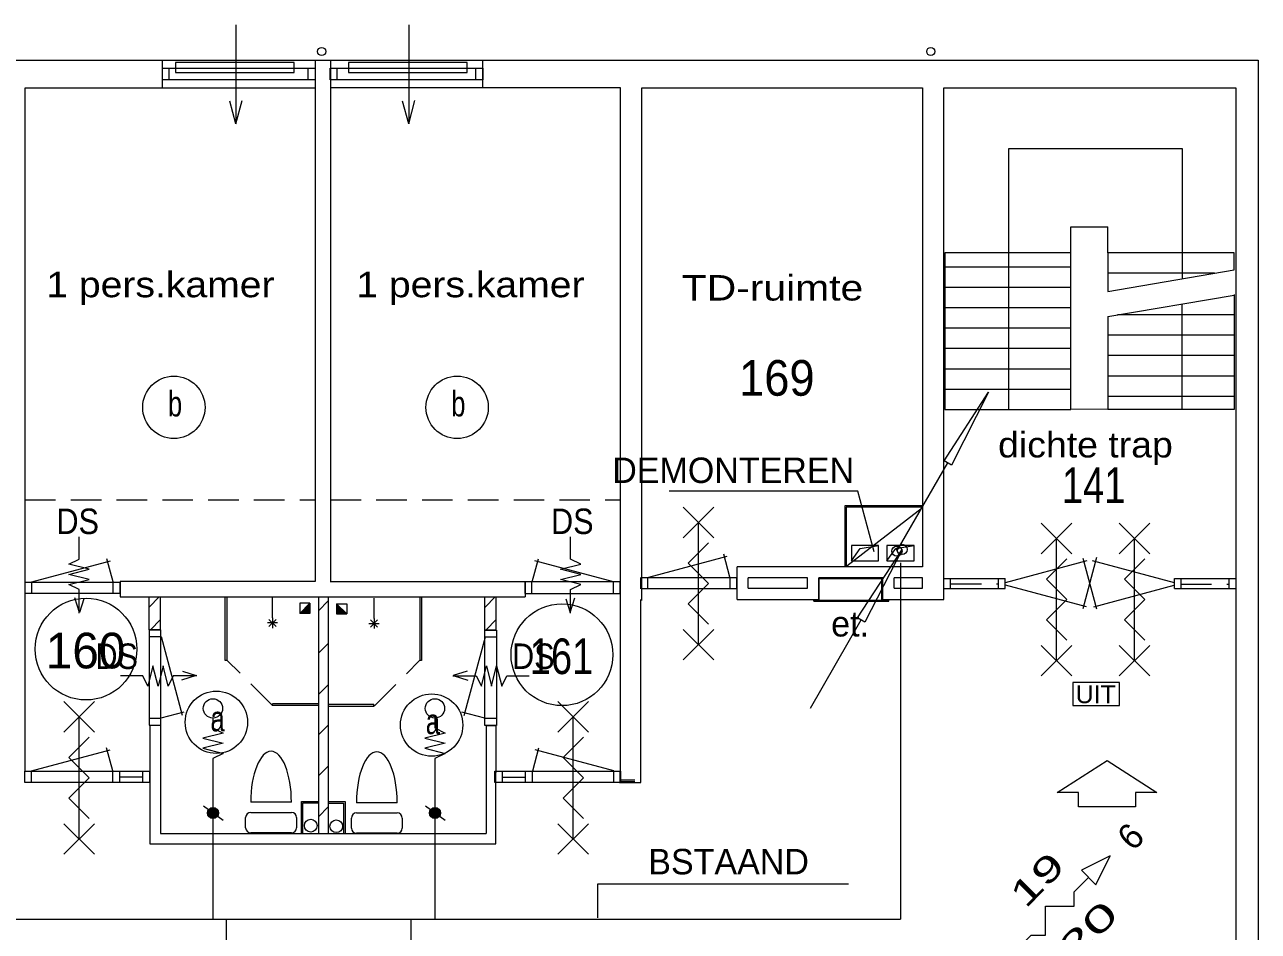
# Model space of a CAD drawing. Extents: x 295824 to 414724, y 24924 to 109024.
# Drawn here: x 320086 to 332210, y 70606 to 79510 of the extents above; entities that cross this region are included whole.
import ezdxf
from ezdxf.enums import TextEntityAlignment as Align

# ---------------------------------------------------------------- set-up
doc = ezdxf.new("R2010")
doc.units = 0
doc.header["$LTSCALE"] = 100
doc.linetypes.add('MEDIUM_DASHED', pattern=[4.5, 3, -1.5])
for name, color, linetype, lineweight in [('1', 7, 'Continuous', 13), ('16', 7, 'Continuous', 13), ('24', 7, 'Continuous', 13), ('61', 7, 'Continuous', 13)]:
    doc.layers.add(name, color=color, linetype=linetype, lineweight=lineweight)

msp = doc.modelspace()

# ---------------------------------------------------------------- hatches: boundary and pattern name
at = {"layer": '24'}
for points in [[(321990.4, 71768.1, 1), (321881.8, 71768.1, 1)], [(324172.4, 71768.1, 1), (324063.7, 71768.1, 1)]]:
    msp.add_hatch(color=256, dxfattribs=at).paths.add_polyline_path(points)
at = {"layer": '61'}
for points in [[(322789.4, 73728.2), (322889.4, 73828.2), (322889.4, 73728.2)], [(323251.9, 73722.8), (323151.9, 73822.8), (323151.9, 73722.8)]]:
    msp.add_hatch(color=256, dxfattribs=at).paths.add_polyline_path(points)

# ---------------------------------------------------------------- linework, layer by layer
at = {"layer": '1'}
for p, q in [((328658.4, 74340.1), (329158.4, 75206.1)), ((327808.4, 72797.7), (328308.4, 73663.7)), ((321936.1, 71736.8), (321936.1, 70726.3)), ((324118, 71730.1), (324118, 70726.3)), ((322069.3, 69843.4), (322069.3, 70726.3)), ((323884.9, 69838.4), (323884.9, 70726.3))]:
    msp.add_line(p, q, dxfattribs=at)
for points in [[(329558.4, 75899.1), (329194.4, 75185.1), (329122.4, 75227.1)], [(328708.4, 74356.7), (328344.4, 73642.7), (328272.4, 73684.7)]]:
    msp.add_lwpolyline(points, close=True, dxfattribs=at)
msp.add_lwpolyline([(328433.5, 74331.1), (328273.3, 74928.7), (326419.8, 74928.7)], dxfattribs=at)
for centre in [(328658.4, 74339.8), (328708.4, 74356.4)]:
    msp.add_circle(centre, 50, dxfattribs=at)
at = {"layer": '16'}
for p, q in [((320520.3, 74111.7), (320720.3, 74161.7)), ((325550.6, 74111.7), (325350.6, 74161.7)), ((321396.7, 73013.5), (321346.7, 73213.5)), ((324674.2, 73013.5), (324724.2, 73213.5))]:
    msp.add_line(p, q, dxfattribs=at)
at = {"layer": '24'}
for p, q in [((322161, 78534.5), (322101.4, 78756.9)), ((323859.9, 78534.5), (323800.3, 78756.9)), ((328693.9, 74223.5), (328693.9, 70726.3)), ((320623.7, 73736.3), (320578.6, 73880.4)), ((320666.1, 73872.1), (320623.7, 73736.3)), ((325404.8, 73872.1), (325447.2, 73736.3)), ((325447.2, 73736.3), (325492.2, 73880.4)), ((321772.1, 73116.9), (321627.9, 73071.9)), ((321636.3, 73159.3), (321772.1, 73116.9)), ((324434.5, 73159.3), (324298.7, 73116.9)), ((324298.7, 73116.9), (324442.9, 73071.9)), ((321936.1, 72253.5), (321936.1, 71714.1)), ((324118, 72253.5), (324118, 71745.1)), ((321844.5, 71838.9), (322036, 71697.3)), ((324026.4, 71838.9), (324218, 71697.3)), ((304097.2, 70726.3), (328693.9, 70726.3))]:
    msp.add_line(p, q, dxfattribs=at)
for points in [[(322161, 79509.5), (322161, 78534.5), (322222.6, 78764.7)], [(323859.9, 79509.5), (323859.9, 78534.5), (323921.6, 78764.7)], [(320720.3, 74161.7), (320520.3, 74211.7), (320620.3, 74261.7), (320620.3, 74480.4)], [(325350.6, 74161.7), (325550.6, 74211.7), (325450.6, 74261.7), (325450.6, 74480.4)], [(328210.5, 74245.1), (328296.9, 74365.1), (328477.8, 74394.6)], [(328560.2, 74245.1), (328646.7, 74365.1), (328827.5, 74394.6)], [(320620.3, 73730.4), (320620.3, 73961.7), (320520.3, 74011.7), (320720.3, 74061.7), (320520.3, 74111.7)], [(325450.6, 73730.4), (325450.6, 73961.7), (325550.6, 74011.7), (325350.6, 74061.7), (325550.6, 74111.7)], [(321346.7, 73213.5), (321296.7, 73013.5), (321246.7, 73113.5), (321027.9, 73113.5)], [(321777.9, 73113.5), (321546.7, 73113.5), (321496.7, 73013.5), (321446.7, 73213.5), (321396.7, 73013.5)], [(324292.9, 73113.5), (324524.2, 73113.5), (324574.2, 73013.5), (324624.2, 73213.5), (324674.2, 73013.5)], [(324724.2, 73213.5), (324774.2, 73013.5), (324824.2, 73113.5), (325042.9, 73113.5)], [(321936.1, 72703.5), (321936.1, 72603.5), (322036.1, 72553.5), (321836.1, 72503.5), (322036.1, 72453.5), (321836.1, 72403.5), (322036.1, 72353.5), (321936.1, 72303.5), (321936.1, 72253.5)], [(324118, 72703.5), (324118, 72603.5), (324218, 72553.5), (324018, 72503.5), (324218, 72453.5), (324018, 72403.5), (324218, 72353.5), (324118, 72303.5), (324118, 72253.5)], [(325717.8, 70738.4), (325717.8, 71071.8), (328182.9, 71071.8)]]:
    msp.add_lwpolyline(points, dxfattribs=at)
for points in [[(321569.6, 79038.7), (322735.6, 79038.7), (322735.6, 79138.7), (321569.6, 79138.7)], [(323268.6, 79038.7), (324434.5, 79038.7), (324434.5, 79138.7), (323268.6, 79138.7)], [(328210.5, 74245.1), (328477.8, 74245.1), (328477.8, 74394.6), (328210.5, 74394.6)], [(328560.2, 74245.1), (328827.5, 74245.1), (328827.5, 74394.6), (328560.2, 74394.6)]]:
    msp.add_lwpolyline(points, close=True, dxfattribs=at)
for centre, radius in [((321936.1, 72795.2), 95), ((324118, 72795.2), 95), ((321936.1, 71768.1), 54.3), ((324118.1, 71768.1), 54.3)]:
    msp.add_circle(centre, radius, dxfattribs=at)
at = {"layer": '61'}
for p, q in [((321440.7, 78890.8), (321440.7, 79160.8)), ((321507.4, 78969), (321507.4, 79082.9)), ((322872.5, 78968.4), (322872.5, 79082.4)), ((322940.1, 79160.6), (322940.1, 74040.8)), ((323090.1, 79153), (323090.1, 74040.8)), ((323156, 78969.4), (323156, 79083.4)), ((324520.3, 78969.1), (324520.3, 79082.7)), ((324588.7, 78890.8), (324588.7, 79160.9)), ((332210.1, 79160.8), (332210.1, 62296.5)), ((320090.1, 78890.8), (322940.1, 78890.8)), ((320090.1, 72179.8), (320090.1, 78890.8)), ((325940.1, 78890.8), (323090.1, 78890.8)), ((325940.1, 72065.8), (325940.1, 78890.8)), ((330368.9, 77267.8), (330368.9, 77525.8)), ((330368.9, 77525.8), (330732.6, 77525.8)), ((330732.6, 77267.8), (330732.6, 77525.8)), ((331972.5, 77267.8), (330732.6, 77267.8)), ((331972.5, 77100.5), (331972.5, 77267.8)), ((329129, 77131.4), (330368.9, 77131.4)), ((330732.6, 76889.3), (331972.5, 77100.5)), ((331780.5, 77067.8), (330732.6, 77067.8)), ((329129, 76931.4), (330368.9, 76931.4)), ((330729.7, 76643), (331972.5, 76854.7)), ((331459.8, 76767.4), (331459.8, 75733.3)), ((329129, 76731.4), (330368.9, 76731.4)), ((331975.6, 76659.4), (330826.3, 76659.4)), ((329129, 76531.4), (330368.9, 76531.4)), ((331975.6, 76459.4), (330729.7, 76459.4)), ((329129, 76331.4), (330368.9, 76331.4)), ((331975.6, 76259.4), (330729.7, 76259.4)), ((329129, 76131.4), (330368.9, 76131.4)), ((331975.6, 76059.4), (330729.7, 76059.4)), ((329129, 75931.4), (330368.9, 75931.4)), ((331975.6, 75859.4), (330729.7, 75859.4)), ((329129, 75731.4), (330368.9, 75731.4)), ((326857.7, 74771.3), (326557.7, 74471.3)), ((326557.7, 74771.3), (326857.7, 74471.3)), ((328910.1, 74785.8), (328145.1, 74785.8)), ((328145.1, 74785.8), (328145.1, 74185.8)), ((328910.1, 74770.8), (328160.1, 74770.8)), ((328160.1, 74770.8), (328160.1, 74185.8)), ((328908.7, 74765.7), (328165.8, 74191.8)), ((326707.7, 73421.3), (326707.7, 74621.3)), ((330376.8, 74613.9), (330076.8, 74313.9)), ((330076.8, 74613.9), (330376.8, 74313.9)), ((331143.5, 74613.9), (330843.5, 74313.9)), ((330843.5, 74613.9), (331143.5, 74313.9)), ((330226.8, 73263.9), (330226.8, 74463.9)), ((330993.5, 73263.9), (330993.5, 74463.9)), ((320156.3, 74036.8), (320929, 74243.8)), ((320954.7, 74037.4), (320893.9, 74264.3)), ((325074.1, 74038.5), (325134.9, 74265.4)), ((325872.5, 74037.9), (325099.8, 74244.9)), ((326218.7, 74082.5), (326991.5, 74289.6)), ((327017.1, 74083.1), (326956.4, 74310)), ((329725.3, 74030.5), (330529.4, 74246)), ((330621.8, 73771.1), (330488.5, 74268.5)), ((330489.1, 73776), (330623.8, 74278.7)), ((330578.4, 74246), (331383.5, 74030.3)), ((326142.6, 73967.9), (326142.6, 74081.9)), ((326151.2, 74081.9), (327086.5, 74081.9)), ((326210.9, 73967.9), (326210.9, 74081.9)), ((327019.5, 73967.9), (327019.5, 74081.9)), ((327086.5, 73967.9), (327086.5, 74081.9)), ((328910.1, 74185.8), (327087.4, 74185.8)), ((327087.4, 73865.8), (327087.4, 74185.8)), ((320157, 73922.2), (320157, 74036.2)), ((320957, 73922.2), (320957, 74036.2)), ((321024, 73922.2), (321024, 74036.2)), ((325004.7, 73923.2), (325004.7, 74037.2)), ((325071.7, 73923.2), (325071.7, 74037.2)), ((325871.7, 73923.2), (325871.7, 74037.2)), ((327086.5, 73967.9), (326151.2, 73967.9)), ((327196.2, 73975.8), (327196.2, 74075.8)), ((327780.1, 74075.8), (327196.2, 74075.8)), ((327196.2, 73975.8), (327780.1, 73975.8)), ((327780.1, 73975.8), (327780.1, 74075.8)), ((327890.1, 73865.8), (327890.1, 74075.8)), ((328520.1, 74075.8), (327890.1, 74075.8)), ((327895, 73859.2), (327895, 74070.9)), ((327895, 74070.9), (328510.1, 74070.9)), ((328510.1, 73859.2), (328510.1, 74070.9)), ((328520.1, 73865.8), (328520.1, 74075.8)), ((328908.2, 74075.8), (328630.1, 74075.8)), ((328630.1, 73975.8), (328630.1, 74075.8)), ((328630.1, 73975.8), (328908.2, 73975.8)), ((328908.2, 73975.8), (328908.2, 74075.8)), ((329120.8, 74071.5), (329723.3, 74071.5)), ((329120.8, 73971.5), (329723.3, 73971.5)), ((329186.3, 73971.5), (329186.3, 74071.5)), ((329657.7, 73971.5), (329657.7, 74071.5)), ((329723.3, 73971.5), (329723.3, 74071.5)), ((329723.4, 74007.3), (330517.1, 73794.6)), ((330593.7, 73792.7), (331383.5, 74004.3)), ((331384.7, 73971.5), (331384.7, 74071.5)), ((331384.7, 74071.5), (331990.1, 74071.5)), ((331384.7, 73971.5), (331990.1, 73971.5)), ((331451.5, 73971.6), (331451.5, 74070.6)), ((331923.1, 73971.2), (331923.1, 74071.2)), ((321309.2, 73789.9), (321408.9, 73889.6)), ((321310.7, 73566.1), (321310.7, 73890.2)), ((321310.7, 73890.2), (321420.7, 73890.2)), ((321420.7, 73566.1), (321420.7, 73890.2)), ((322071.9, 73890.5), (322071.9, 73270)), ((322521.8, 73684), (322521.8, 73884)), ((322973.8, 73890.8), (322973.8, 71565.8)), ((322974.4, 73754.6), (323070.1, 73850.4)), ((323070.1, 73890.8), (323070.1, 71565.8)), ((323519.5, 73678.6), (323519.5, 73878.6)), ((323969.4, 73885.1), (323969.4, 73264.6)), ((324609.7, 73566.1), (324609.7, 73890.2)), ((324609.7, 73890.2), (324719.6, 73890.2)), ((324611.4, 73789.9), (324711.1, 73889.6)), ((324719.6, 73566.1), (324719.6, 73890.2)), ((326141.5, 72065.8), (326141.5, 73865.8)), ((327087.4, 73865.8), (327890.1, 73865.8)), ((327840.7, 73858.9), (328577.6, 73858.9)), ((327840.7, 73848.9), (327840.7, 73858.9)), ((327840.7, 73848.9), (328577.6, 73848.9)), ((328520.1, 73865.8), (329120.1, 73865.8)), ((328577.6, 73848.9), (328577.6, 73858.9)), ((331990.1, 73865.8), (331990.1, 69402.2)), ((321321.5, 73567.3), (321421.2, 73667)), ((322571.8, 73634), (322471.8, 73634)), ((322557.2, 73669.3), (322486.4, 73598.6)), ((322557.2, 73598.6), (322486.4, 73669.3)), ((322521.8, 73684), (322521.8, 73584)), ((323469.5, 73628.6), (323569.5, 73628.6)), ((323484.1, 73664), (323554.9, 73593.3)), ((323484.1, 73593.3), (323554.9, 73664)), ((323519.5, 73678.6), (323519.5, 73578.6)), ((324620, 73567.3), (324719.7, 73667)), ((321308.9, 73565.2), (321308.9, 72632.8)), ((321308.9, 73499.8), (321422.9, 73499.8)), ((321310.7, 73566.1), (321420.7, 73566.1)), ((321426.1, 73500.6), (321633.1, 72727.8)), ((324610.3, 73496.3), (324403.2, 72723.6)), ((324722.4, 73495.6), (324608.4, 73495.6)), ((324609, 73562.6), (324723, 73562.6)), ((324609.7, 73566.1), (324719.6, 73566.1)), ((324722.4, 73562.6), (324722.4, 72628.6)), ((326857.7, 73571.3), (326557.7, 73271.3)), ((326557.7, 73571.3), (326857.7, 73271.3)), ((322974.4, 73336.5), (323070.1, 73432.3)), ((330376.8, 73413.9), (330076.8, 73113.9)), ((330076.8, 73413.9), (330376.8, 73113.9)), ((331143.5, 73413.9), (330843.5, 73113.9)), ((330843.5, 73413.9), (331143.5, 73113.9)), ((322974.4, 72931.9), (323070.1, 73027.7)), ((320770.9, 72863), (320470.9, 72563)), ((320470.9, 72863), (320770.9, 72563)), ((321426.7, 72702.2), (321653.6, 72762.9)), ((322972, 72840.5), (322522.8, 72840.5)), ((322522.8, 72822.5), (322522.8, 72840.5)), ((322972.3, 72822.5), (322522.8, 72822.5)), ((323069, 72817.1), (323518.5, 72817.1)), ((323069.3, 72835.1), (323518.5, 72835.1)), ((323518.5, 72817.1), (323518.5, 72835.1)), ((324609.7, 72697.9), (324382.8, 72758.7)), ((325626.8, 72863), (325326.8, 72563)), ((325326.8, 72863), (325626.8, 72563)), ((320620.9, 71513), (320620.9, 72713)), ((321308.9, 72699.8), (321422.9, 72699.8)), ((321314.9, 72629.2), (321314.9, 72063.4)), ((321314.9, 72629.2), (321420.1, 72629.2)), ((322974.4, 72535.9), (323070.1, 72631.7)), ((324722.4, 72695.6), (324608.4, 72695.6)), ((324620.1, 72627.8), (324620.1, 71565.8)), ((324620.1, 72627.8), (324714.9, 72627.8)), ((324714.9, 72627.8), (324714.9, 72165.8)), ((325476.8, 71513), (325476.8, 72713)), ((320152.9, 72180.4), (320925.7, 72387.5)), ((320951.3, 72181), (320890.5, 72407.9)), ((325078.7, 72181.1), (325139.4, 72407.9)), ((325877.1, 72180.4), (325104.3, 72387.5)), ((320153.7, 72065.8), (320153.7, 72179.8)), ((320953.7, 72065.8), (320953.7, 72179.8)), ((321020.7, 72065.8), (321020.7, 72179.8)), ((321246.7, 72065.8), (321246.7, 72179.8)), ((322974.4, 72132.6), (323070.1, 72228.3)), ((324783.3, 72065.8), (324783.3, 72179.8)), ((325009.3, 72065.8), (325009.3, 72179.8)), ((325076.3, 72065.8), (325076.3, 72179.8)), ((325876.3, 72065.8), (325876.3, 72179.8)), ((321246.7, 72119.9), (321020.7, 72119.9)), ((324783.3, 72119.9), (325009.3, 72119.9)), ((325931.5, 72065.8), (326141.5, 72065.8)), ((325942.4, 72092.1), (326083.6, 72092.1)), ((325942.4, 72077.1), (326083.6, 72077.1)), ((322707.5, 71873.6), (322307.5, 71873.6)), ((322820, 71866.2), (322970, 71866.2)), ((322820, 71566.2), (322820, 71866.2)), ((322974.4, 71731.7), (323070.1, 71827.4)), ((323070.1, 71865.8), (323220.1, 71865.8)), ((323220.1, 71865.8), (323220.1, 71565.8)), ((323746.9, 71868.7), (323346.9, 71868.7)), ((320770.9, 71663), (320470.9, 71363)), ((320470.9, 71663), (320770.9, 71363)), ((322257.5, 71623.6), (322257.5, 71723.6)), ((322307.5, 71773.6), (322707.5, 71773.6)), ((322757.5, 71723.6), (322757.5, 71623.6)), ((323296.9, 71618.7), (323296.9, 71718.7)), ((323346.9, 71768.7), (323746.9, 71768.7)), ((323796.9, 71718.7), (323796.9, 71618.7)), ((325626.8, 71663), (325326.8, 71363)), ((325326.8, 71663), (325626.8, 71363)), ((322707.5, 71573.6), (322307.5, 71573.6)), ((323746.9, 71568.7), (323346.9, 71568.7))]:
    msp.add_line(p, q, dxfattribs=at)
at = {"layer": '61', "linetype": 'MEDIUM_DASHED'}
for p, q in [((320089.5, 74844.1), (322938.6, 74844.1)), ((323091.9, 74844.1), (325938.9, 74844.1)), ((329188.3, 74017.9), (329658.2, 74017.9)), ((331450.5, 74015.4), (331922.9, 74015.4)), ((322520.8, 72822.9), (322073.9, 73269.8)), ((323520.5, 72817.6), (323967.4, 73264.5))]:
    msp.add_line(p, q, dxfattribs=at)
at = {"layer": '61'}
for points in [[(301796.6, 66927.7), (301820.1, 79160.8), (332210.1, 79160.8)], [(326150.1, 73853.8), (326150.1, 78890.8), (328910.1, 78890.8), (328910.1, 74185.8)], [(329120.1, 73865.8), (329120.1, 78890.8), (331990.1, 78890.8), (331990.1, 73864.1)], [(329757.2, 75731.4), (329757.2, 78292.1), (331460, 78292.1), (331460, 77013.2)], [(331972.5, 77267.8), (330732.6, 77267.8), (330732.6, 76889.3)], [(330729.7, 75733.3), (331975.6, 75733.3), (331975.6, 76859.4)], [(330729.7, 76643), (330729.7, 75733.3), (330368.9, 75731.4)], [(326807.7, 73621.3), (326607.7, 73821.3), (326807.7, 74021.3), (326607.7, 74221.3), (326807.7, 74421.3)], [(330326.8, 73463.9), (330126.8, 73663.9), (330326.8, 73863.9), (330126.8, 74063.9), (330326.8, 74263.9)], [(331093.5, 73463.9), (330893.5, 73663.9), (331093.5, 73863.9), (330893.5, 74063.9), (331093.5, 74263.9)], [(320090, 73922.2), (320090, 74036.2), (321024, 74036.2)], [(321024, 73922.2), (320090, 73922.2), (320090, 74036.2)], [(322939.9, 74040.8), (321024.9, 74040.8), (321024.9, 73890.8), (325004.2, 73890.8)], [(323089.9, 74040.8), (325004.2, 74040.8), (325004.2, 73890.8)], [(325938.7, 73923.2), (325938.7, 74037.2), (325004.7, 74037.2)], [(325004.7, 73923.2), (325938.7, 73923.2), (325938.7, 74037.2)], [(322053.9, 73890.5), (322053.9, 73270), (322071.9, 73270)], [(323987.4, 73885.1), (323987.4, 73264.6), (323969.4, 73264.6)], [(322889.4, 73828.2), (322889.4, 73728.2), (322789.4, 73728.2)], [(323151.9, 73822.8), (323151.9, 73722.8), (323251.9, 73722.8)], [(321420.1, 72629.2), (321420.1, 71565.8), (324620.1, 71565.8)], [(320720.9, 71713), (320520.9, 71913), (320720.9, 72113), (320520.9, 72313), (320720.9, 72513)], [(325576.8, 71713), (325376.8, 71913), (325576.8, 72113), (325376.8, 72313), (325576.8, 72513)], [(321314.9, 72065.8), (321314.9, 71465.8), (324714.9, 71465.8), (324714.9, 72065.8)], [(322805, 71566.2), (322805, 71881.2), (322970, 71881.2)], [(323070.1, 71880.8), (323235.1, 71880.8), (323235.1, 71565.8)], [(329552.8, 70144.4), (329977, 70568.7), (330118.4, 70568.7), (330118.4, 70851.5), (330401.3, 70851.5), (330401.3, 70992.9), (330542.7, 71134.3)]]:
    msp.add_lwpolyline(points, dxfattribs=at)
for points in [[(321440.6, 78968.9), (321440.6, 79082.9), (322939.3, 79082.9), (322939.3, 78968.9)], [(323089.6, 78969.1), (323089.6, 79083.1), (324589, 79083.1), (324589, 78969.1)], [(330368.9, 77267.8), (329129, 77267.8), (329129, 75731.4), (330368.9, 75731.4)], [(322889.4, 73828.2), (322789.4, 73828.2), (322789.4, 73728.2)], [(322789.4, 73728.2), (322889.4, 73828.2), (322889.4, 73728.2)], [(323151.9, 73822.8), (323251.9, 73822.8), (323251.9, 73722.8)], [(323251.9, 73722.8), (323151.9, 73822.8), (323151.9, 73722.8)], [(321308.9, 72631.9), (321422.9, 72631.9), (321422.9, 73565.9), (321308.9, 73565.9)], [(324722.4, 73562.6), (324722.4, 72628.6), (324608.4, 72628.6), (324608.4, 73562.6)], [(330387.6, 72825), (330847.2, 72825), (330847.2, 73049.7), (330387.6, 73049.7)], [(331003.4, 71828.6), (330443.4, 71828.6), (330443.4, 71968.6), (330233.4, 71968.6), (330723.4, 72283.6), (331213.4, 71968.6), (331003.4, 71968.6)], [(320086.7, 72065.8), (320086.7, 72179.8), (321313, 72179.8), (321313, 72065.8)], [(320086.7, 72065.8), (320086.7, 72179.8), (321313, 72179.8), (321313, 72065.8)], [(324708, 72065.8), (324708, 72179.8), (325935, 72179.8), (325935, 72065.8)], [(324716.3, 72065.8), (324716.3, 72179.8), (325943.3, 72179.8), (325943.3, 72065.8)], [(330472, 71205.1), (330613.4, 71063.7), (330754.8, 71346.5)]]:
    msp.add_lwpolyline(points, close=True, dxfattribs=at)
for centre, radius in [((323005.3, 79245.8), 40), ((328990.8, 79245.8), 40), ((321552.2, 75751.7), 306.3), ((324336.3, 75751.7), 306.3), ((320688.9, 73377.9), 500), ((325366.2, 73322.2), 500), ((321969.8, 72659), 306.3), ((324085.7, 72631.2), 306.3), ((322897.6, 71643.7), 62.5), ((323147.6, 71638.2), 62.5)]:
    msp.add_circle(centre, radius, dxfattribs=at)
for centre, start, end in [((322307.5, 71723.6), 90, 180), ((322707.5, 71723.6), 0, 90), ((323346.9, 71718.7), 90, 180), ((323746.9, 71718.7), 0, 90), ((322307.5, 71623.6), 180, 270), ((322707.5, 71623.6), 270, 0), ((323346.9, 71618.7), 180, 270), ((323746.9, 71618.7), 270, 0)]:
    msp.add_arc(centre, 50, start, end, dxfattribs=at)
for centre in [(322507.5, 71873.6), (323546.9, 71868.7)]:
    msp.add_ellipse(centre, major_axis=(0, 500), ratio=0.4, start_param=4.712389, end_param=7.8539816, dxfattribs=at)

# ---------------------------------------------------------------- texts
at = {"layer": '24'}
for s, p in [('DEMONTEREN', (325860.5, 75008.7)), ('BSTAAND', (326214.6, 71165.3))]:
    msp.add_text(s, height=250, dxfattribs=at).set_placement(p)
at = {"layer": '24', "width": 0.9}
for p in [(320398.4, 74507.5), (325259, 74507.5), (320781.5, 73182.5), (324875.9, 73182.5)]:
    msp.add_text('DS', height=250, dxfattribs=at).set_placement(p)
at = {"layer": '61'}
for s, height, width, p in [('1 pers.kamer', 250, 1.15, (320298.2, 76832.7)), ('1 pers.kamer', 250, 1.15, (323345, 76832.7)), ('TD-ruimte', 250, 1.2, (326544.2, 76800.7)), ('b', 250, 0.75, (321494.2, 75662.5)), ('b', 250, 0.75, (324278.3, 75662.5)), ('dichte trap', 250, 1.1, (329652.6, 75259.5)), ('UIT', 175, 1.05, (330414.3, 72846.4)), ('a', 250, 0.75, (321911.8, 72569.9)), ('a', 250, 0.75, (324027.7, 72542))]:
    msp.add_text(s, height=height, dxfattribs=dict(at, width=width)).set_placement(p)
for s, width, p in [('169', 0.95, (327478.1, 75865.7)), ('141', 0.8, (330591.7, 74811.7)), ('161', 0.8, (325361.9, 73132.3))]:
    msp.add_text(s, height=350, dxfattribs=dict(at, width=width)).set_placement(p, align=Align.CENTER)
msp.add_text('et.', height=250, dxfattribs=at).set_placement((328011.9, 73501.2))
msp.add_text('160', height=350, dxfattribs=at).set_placement((320684.6, 73188.1), align=Align.CENTER)
msp.add_text('6', height=250, rotation=45, dxfattribs=at).set_placement((330977.5, 71384.2))
for s, width, p in [('19', 1.55, (329921.2, 70822.7)), ('20', 1.75, (330393.5, 70294.3))]:
    msp.add_text(s, height=250, rotation=45, dxfattribs=dict(at, width=width)).set_placement(p)

doc.saveas('drawing.dxf')
